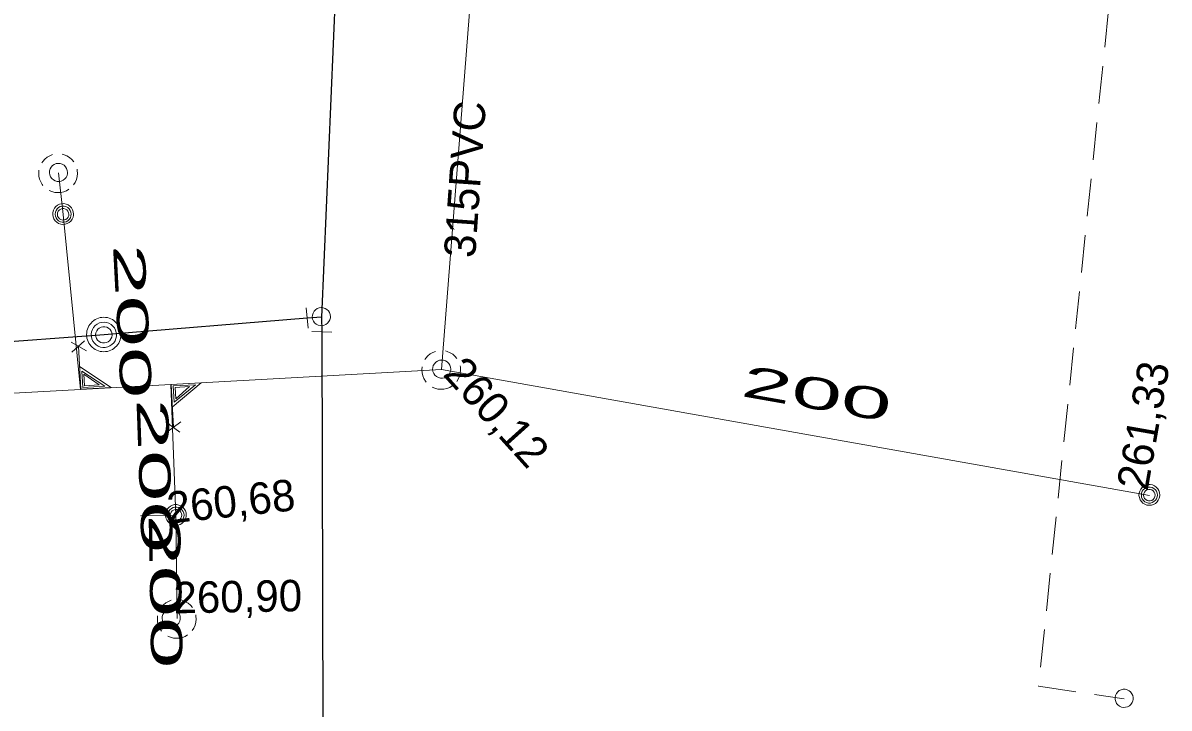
# Model space of a CAD drawing. Extents: x -732096 to -731933, y -1048703 to -1047964.
# Drawn here: x -732046.89 to -732017.73, y -1048047.02 to -1048029.6 of the extents above; entities that cross this region are included whole.
import ezdxf

# ---------------------------------------------------------------- set-up
doc = ezdxf.new("R2010")
doc.units = 0
doc.header["$LTSCALE"] = 0.32
doc.linetypes.add('MEDIUM_DASHED', pattern=[4.5, 3, -1.5])
doc.layers.add('1', color=7, linetype='Continuous')
for name, color, linetype, lineweight in [('18', 7, 'Continuous', 13), ('20', 7, 'Continuous', 13), ('49', 7, 'Continuous', 13), ('8', 7, 'Continuous', 13)]:
    doc.layers.add(name, color=color, linetype=linetype, lineweight=lineweight)

msp = doc.modelspace()

# ---------------------------------------------------------------- linework, layer by layer
at = {"layer": '18'}
for p, q in [((-732045.326, -1048037.679), (-732045.646, -1048037.966)), ((-732045.664, -1048037.71), (-732045.28, -1048037.934)), ((-732042.897, -1048039.999), (-732043.246, -1048039.749)), ((-732043.235, -1048040.006), (-732042.878, -1048039.742))]:
    msp.add_line(p, q, dxfattribs=at)
for points in [[(-732046.142, -1048032.947), (-732046.213, -1048032.975), (-732046.279, -1048033.014), (-732046.34, -1048033.062), (-732046.391, -1048033.119), (-732046.414, -1048033.153)], [(-732045.6, -1048033.13), (-732045.651, -1048033.072), (-732045.708, -1048033.022), (-732045.774, -1048032.981), (-732045.845, -1048032.952), (-732045.894, -1048032.938)], [(-732045.605, -1048033.716), (-732045.565, -1048033.651), (-732045.534, -1048033.581), (-732045.514, -1048033.506), (-732045.507, -1048033.43), (-732045.512, -1048033.353), (-732045.517, -1048033.318)], [(-732046.487, -1048033.339), (-732046.492, -1048033.416), (-732046.487, -1048033.493), (-732046.47, -1048033.568), (-732046.441, -1048033.639), (-732046.401, -1048033.705), (-732046.386, -1048033.727)], [(-732046.228, -1048033.856), (-732046.159, -1048033.887), (-732046.083, -1048033.906), (-732046.007, -1048033.913), (-732045.931, -1048033.908), (-732045.855, -1048033.891), (-732045.784, -1048033.863), (-732045.723, -1048033.828)], [(-732045.48, -1048037.816), (-732045.42, -1048038.911), (-732044.65, -1048038.868), (-732045.451, -1048038.334)], [(-732036.392, -1048037.947), (-732036.463, -1048037.975), (-732036.529, -1048038.014), (-732036.59, -1048038.062), (-732036.641, -1048038.119), (-732036.664, -1048038.153)], [(-732035.85, -1048038.13), (-732035.901, -1048038.072), (-732035.958, -1048038.022), (-732036.024, -1048037.981), (-732036.095, -1048037.952), (-732036.144, -1048037.938)], [(-732045.394, -1048038.449), (-732045.371, -1048038.864), (-732044.807, -1048038.833), (-732045.394, -1048038.448)], [(-732045.342, -1048038.53), (-732045.326, -1048038.82), (-732044.956, -1048038.8), (-732045.344, -1048038.53)], [(-732036.737, -1048038.339), (-732036.742, -1048038.416), (-732036.737, -1048038.493), (-732036.72, -1048038.568), (-732036.691, -1048038.639), (-732036.651, -1048038.705), (-732036.636, -1048038.727)], [(-732035.855, -1048038.716), (-732035.815, -1048038.651), (-732035.784, -1048038.581), (-732035.764, -1048038.506), (-732035.757, -1048038.43), (-732035.762, -1048038.353), (-732035.767, -1048038.318)], [(-732043.064, -1048039.879), (-732043.124, -1048038.786), (-732042.355, -1048038.744), (-732043.092, -1048039.363)], [(-732043.049, -1048039.241), (-732043.071, -1048038.827), (-732042.506, -1048038.796), (-732043.048, -1048039.243)], [(-732043.006, -1048039.156), (-732043.022, -1048038.864), (-732042.651, -1048038.844), (-732043.007, -1048039.156)], [(-732036.478, -1048038.856), (-732036.409, -1048038.887), (-732036.333, -1048038.906), (-732036.257, -1048038.913), (-732036.181, -1048038.908), (-732036.105, -1048038.891), (-732036.034, -1048038.863), (-732035.973, -1048038.828)], [(-732043.122, -1048044.277), (-732043.193, -1048044.305), (-732043.26, -1048044.344), (-732043.32, -1048044.392), (-732043.371, -1048044.449), (-732043.395, -1048044.483)], [(-732042.581, -1048044.46), (-732042.631, -1048044.402), (-732042.689, -1048044.352), (-732042.754, -1048044.311), (-732042.825, -1048044.282), (-732042.874, -1048044.268)], [(-732043.467, -1048044.669), (-732043.473, -1048044.746), (-732043.468, -1048044.823), (-732043.451, -1048044.898), (-732043.422, -1048044.969), (-732043.382, -1048045.035), (-732043.366, -1048045.057)], [(-732042.586, -1048045.046), (-732042.545, -1048044.981), (-732042.514, -1048044.911), (-732042.495, -1048044.836), (-732042.487, -1048044.76), (-732042.492, -1048044.683), (-732042.498, -1048044.648)], [(-732043.209, -1048045.186), (-732043.139, -1048045.217), (-732043.064, -1048045.236), (-732042.988, -1048045.243), (-732042.911, -1048045.238), (-732042.836, -1048045.221), (-732042.764, -1048045.193), (-732042.704, -1048045.158)]]:
    msp.add_lwpolyline(points, dxfattribs=at)
for points in [[(-732045.757, -1048033.399), (-732045.764, -1048033.347), (-732045.781, -1048033.297), (-732045.809, -1048033.253), (-732045.848, -1048033.216), (-732045.892, -1048033.189), (-732045.943, -1048033.173), (-732045.995, -1048033.168), (-732046.046, -1048033.175), (-732046.095, -1048033.194), (-732046.139, -1048033.224), (-732046.174, -1048033.263), (-732046.201, -1048033.308), (-732046.215, -1048033.359), (-732046.218, -1048033.411), (-732046.21, -1048033.463), (-732046.19, -1048033.511), (-732046.159, -1048033.554), (-732046.12, -1048033.589), (-732046.073, -1048033.613), (-732046.022, -1048033.627), (-732045.97, -1048033.629), (-732045.919, -1048033.619), (-732045.87, -1048033.597), (-732045.828, -1048033.565), (-732045.796, -1048033.525), (-732045.772, -1048033.478), (-732045.759, -1048033.427)], [(-732045.606, -1048034.457), (-732045.612, -1048034.401), (-732045.629, -1048034.348), (-732045.657, -1048034.299), (-732045.696, -1048034.258), (-732045.742, -1048034.226), (-732045.794, -1048034.204), (-732045.849, -1048034.193), (-732045.905, -1048034.195), (-732045.96, -1048034.208), (-732046.011, -1048034.233), (-732046.055, -1048034.268), (-732046.091, -1048034.311), (-732046.116, -1048034.361), (-732046.131, -1048034.416), (-732046.134, -1048034.472), (-732046.125, -1048034.527), (-732046.104, -1048034.58), (-732046.073, -1048034.626), (-732046.032, -1048034.665), (-732045.985, -1048034.695), (-732045.932, -1048034.714), (-732045.876, -1048034.721), (-732045.82, -1048034.717), (-732045.766, -1048034.7), (-732045.717, -1048034.673), (-732045.675, -1048034.635), (-732045.642, -1048034.59), (-732045.619, -1048034.539), (-732045.607, -1048034.484)], [(-732045.665, -1048034.46), (-732045.671, -1048034.411), (-732045.689, -1048034.365), (-732045.717, -1048034.324), (-732045.754, -1048034.291), (-732045.798, -1048034.269), (-732045.846, -1048034.257), (-732045.895, -1048034.257), (-732045.943, -1048034.269), (-732045.987, -1048034.292), (-732046.024, -1048034.325), (-732046.052, -1048034.366), (-732046.069, -1048034.413), (-732046.075, -1048034.462), (-732046.068, -1048034.511), (-732046.05, -1048034.557), (-732046.022, -1048034.597), (-732045.985, -1048034.63), (-732045.941, -1048034.652), (-732045.892, -1048034.664), (-732045.843, -1048034.663), (-732045.795, -1048034.651), (-732045.752, -1048034.627), (-732045.715, -1048034.594), (-732045.687, -1048034.553), (-732045.671, -1048034.506)], [(-732045.724, -1048034.464), (-732045.73, -1048034.422), (-732045.747, -1048034.384), (-732045.775, -1048034.353), (-732045.809, -1048034.33), (-732045.85, -1048034.319), (-732045.892, -1048034.319), (-732045.932, -1048034.331), (-732045.967, -1048034.354), (-732045.994, -1048034.386), (-732046.011, -1048034.424), (-732046.016, -1048034.465), (-732046.01, -1048034.507), (-732045.992, -1048034.544), (-732045.964, -1048034.576), (-732045.928, -1048034.598), (-732045.888, -1048034.609), (-732045.846, -1048034.608), (-732045.806, -1048034.595), (-732045.772, -1048034.572), (-732045.745, -1048034.539), (-732045.729, -1048034.501)], [(-732036.007, -1048038.399), (-732036.014, -1048038.347), (-732036.031, -1048038.297), (-732036.059, -1048038.253), (-732036.098, -1048038.216), (-732036.142, -1048038.189), (-732036.193, -1048038.173), (-732036.245, -1048038.168), (-732036.296, -1048038.175), (-732036.345, -1048038.194), (-732036.389, -1048038.224), (-732036.424, -1048038.263), (-732036.451, -1048038.308), (-732036.465, -1048038.359), (-732036.468, -1048038.411), (-732036.46, -1048038.463), (-732036.44, -1048038.511), (-732036.409, -1048038.554), (-732036.37, -1048038.589), (-732036.323, -1048038.613), (-732036.272, -1048038.627), (-732036.22, -1048038.629), (-732036.169, -1048038.619), (-732036.12, -1048038.597), (-732036.078, -1048038.565), (-732036.046, -1048038.525), (-732036.022, -1048038.478), (-732036.009, -1048038.427)], [(-732017.966, -1048041.597), (-732017.972, -1048041.541), (-732017.989, -1048041.488), (-732018.017, -1048041.439), (-732018.056, -1048041.398), (-732018.102, -1048041.366), (-732018.154, -1048041.344), (-732018.209, -1048041.333), (-732018.265, -1048041.335), (-732018.32, -1048041.348), (-732018.37, -1048041.373), (-732018.415, -1048041.408), (-732018.451, -1048041.451), (-732018.476, -1048041.501), (-732018.491, -1048041.556), (-732018.494, -1048041.612), (-732018.485, -1048041.667), (-732018.464, -1048041.72), (-732018.433, -1048041.766), (-732018.392, -1048041.805), (-732018.345, -1048041.835), (-732018.292, -1048041.854), (-732018.236, -1048041.861), (-732018.179, -1048041.857), (-732018.125, -1048041.84), (-732018.076, -1048041.813), (-732018.035, -1048041.775), (-732018.002, -1048041.73), (-732017.978, -1048041.679), (-732017.967, -1048041.624)], [(-732018.025, -1048041.6), (-732018.031, -1048041.551), (-732018.049, -1048041.505), (-732018.076, -1048041.464), (-732018.114, -1048041.431), (-732018.157, -1048041.409), (-732018.206, -1048041.397), (-732018.255, -1048041.397), (-732018.303, -1048041.409), (-732018.347, -1048041.432), (-732018.384, -1048041.465), (-732018.412, -1048041.506), (-732018.429, -1048041.553), (-732018.434, -1048041.602), (-732018.428, -1048041.651), (-732018.41, -1048041.697), (-732018.382, -1048041.737), (-732018.345, -1048041.77), (-732018.301, -1048041.792), (-732018.252, -1048041.804), (-732018.203, -1048041.803), (-732018.155, -1048041.791), (-732018.112, -1048041.767), (-732018.075, -1048041.734), (-732018.047, -1048041.693), (-732018.031, -1048041.646)], [(-732018.084, -1048041.604), (-732018.09, -1048041.562), (-732018.107, -1048041.524), (-732018.135, -1048041.493), (-732018.169, -1048041.47), (-732018.21, -1048041.459), (-732018.252, -1048041.459), (-732018.292, -1048041.471), (-732018.326, -1048041.494), (-732018.353, -1048041.526), (-732018.37, -1048041.564), (-732018.375, -1048041.605), (-732018.37, -1048041.647), (-732018.352, -1048041.684), (-732018.324, -1048041.716), (-732018.288, -1048041.738), (-732018.248, -1048041.749), (-732018.206, -1048041.748), (-732018.166, -1048041.735), (-732018.132, -1048041.712), (-732018.105, -1048041.679), (-732018.089, -1048041.641)], [(-732042.736, -1048042.107), (-732042.742, -1048042.051), (-732042.759, -1048041.998), (-732042.788, -1048041.949), (-732042.826, -1048041.908), (-732042.872, -1048041.876), (-732042.924, -1048041.854), (-732042.979, -1048041.843), (-732043.035, -1048041.845), (-732043.09, -1048041.858), (-732043.141, -1048041.883), (-732043.185, -1048041.918), (-732043.221, -1048041.961), (-732043.246, -1048042.011), (-732043.261, -1048042.066), (-732043.264, -1048042.122), (-732043.255, -1048042.177), (-732043.234, -1048042.23), (-732043.203, -1048042.276), (-732043.163, -1048042.315), (-732043.115, -1048042.345), (-732043.062, -1048042.364), (-732043.006, -1048042.371), (-732042.95, -1048042.367), (-732042.896, -1048042.35), (-732042.847, -1048042.323), (-732042.805, -1048042.285), (-732042.772, -1048042.24), (-732042.749, -1048042.189), (-732042.737, -1048042.134)], [(-732042.795, -1048042.11), (-732042.801, -1048042.061), (-732042.819, -1048042.015), (-732042.847, -1048041.974), (-732042.884, -1048041.941), (-732042.928, -1048041.919), (-732042.976, -1048041.907), (-732043.025, -1048041.907), (-732043.073, -1048041.919), (-732043.117, -1048041.942), (-732043.154, -1048041.975), (-732043.182, -1048042.016), (-732043.199, -1048042.063), (-732043.205, -1048042.112), (-732043.198, -1048042.161), (-732043.18, -1048042.207), (-732043.152, -1048042.247), (-732043.115, -1048042.28), (-732043.071, -1048042.302), (-732043.022, -1048042.314), (-732042.973, -1048042.313), (-732042.925, -1048042.301), (-732042.882, -1048042.277), (-732042.845, -1048042.244), (-732042.817, -1048042.203), (-732042.801, -1048042.156)], [(-732042.854, -1048042.114), (-732042.86, -1048042.072), (-732042.877, -1048042.034), (-732042.905, -1048042.003), (-732042.94, -1048041.98), (-732042.98, -1048041.969), (-732043.022, -1048041.969), (-732043.062, -1048041.981), (-732043.097, -1048042.004), (-732043.124, -1048042.036), (-732043.141, -1048042.074), (-732043.146, -1048042.115), (-732043.14, -1048042.157), (-732043.122, -1048042.194), (-732043.094, -1048042.226), (-732043.058, -1048042.248), (-732043.018, -1048042.259), (-732042.976, -1048042.258), (-732042.936, -1048042.245), (-732042.902, -1048042.222), (-732042.875, -1048042.189), (-732042.859, -1048042.151)], [(-732042.889, -1048044.729), (-732042.895, -1048044.677), (-732042.913, -1048044.627), (-732042.941, -1048044.583), (-732042.979, -1048044.546), (-732043.024, -1048044.519), (-732043.074, -1048044.503), (-732043.126, -1048044.498), (-732043.178, -1048044.505), (-732043.227, -1048044.524), (-732043.271, -1048044.554), (-732043.306, -1048044.593), (-732043.332, -1048044.638), (-732043.347, -1048044.689), (-732043.35, -1048044.741), (-732043.342, -1048044.793), (-732043.321, -1048044.841), (-732043.291, -1048044.884), (-732043.251, -1048044.919), (-732043.205, -1048044.943), (-732043.154, -1048044.957), (-732043.102, -1048044.959), (-732043.05, -1048044.949), (-732043.002, -1048044.927), (-732042.96, -1048044.895), (-732042.927, -1048044.855), (-732042.903, -1048044.808), (-732042.891, -1048044.757)]]:
    msp.add_lwpolyline(points, close=True, dxfattribs=at)
at = {"layer": '20'}
msp.add_lwpolyline([(-732072.387, -1048040.394), (-732045.426, -1048038.914), (-732043.129, -1048038.788), (-732036.239, -1048038.41), (-732035.469, -1048028.56)], dxfattribs=at)
msp.add_lwpolyline([(-732072.387, -1048040.394), (-732045.426, -1048038.914), (-732043.129, -1048038.788), (-732036.239, -1048038.41), (-732035.469, -1048028.56)], dxfattribs=at)
at = {"layer": '49'}
for p, q in [((-732018.23, -1048041.61), (-732036.239, -1048038.41)), ((-732018.23, -1048041.61), (-732036.239, -1048038.41)), ((-732043, -1048042.12), (-732043.129, -1048038.788)), ((-732043, -1048042.12), (-732043.129, -1048038.788)), ((-732043.899, -1048042.13), (-732043, -1048042.12)), ((-732043.899, -1048042.13), (-732043, -1048042.12)), ((-732042.969, -1048044.74), (-732043, -1048042.12)), ((-732042.969, -1048044.74), (-732043, -1048042.12))]:
    msp.add_line(p, q, dxfattribs=at)
msp.add_lwpolyline([(-732045.989, -1048033.41), (-732045.87, -1048034.47), (-732045.426, -1048038.914)], dxfattribs=at)
msp.add_lwpolyline([(-732045.989, -1048033.41), (-732045.87, -1048034.47), (-732045.426, -1048038.914)], dxfattribs=at)
at = {"layer": '8', "lineweight": 25}
for p, q in [((-732039.66, -1048037.1), (-732044.829, -1048037.53)), ((-732039.3, -1048037.077), (-732039.66, -1048037.1)), ((-732039.3, -1048037.077), (-732039.289, -1048037.45))]:
    msp.add_line(p, q, dxfattribs=at)
at = {"layer": '8'}
for p, q in [((-732039.636, -1048037.358), (-732039.683, -1048036.843)), ((-732039.029, -1048037.457), (-732039.546, -1048037.442))]:
    msp.add_line(p, q, dxfattribs=at)
at = {"layer": '8', "lineweight": 25}
for points in [[(-732033.399, -1047999.11), (-732033.26, -1048005.79), (-732035.475, -1048012.689), (-732038.309, -1048021.518), (-732038.774, -1048026.833), (-732038.94, -1048028.735), (-732039.3, -1048037.077)], [(-732044.829, -1048037.53), (-732057.629, -1048038.48), (-732069.423, -1048038.886), (-732072.139, -1048038.979)], [(-732039.289, -1048037.45), (-732039.26, -1048047.48), (-732037.5, -1048060.59), (-732034.1, -1048071.04), (-732029.18, -1048078.35)]]:
    msp.add_lwpolyline(points, dxfattribs=at)
at = {"layer": '8', "linetype": 'MEDIUM_DASHED'}
msp.add_lwpolyline([(-732019.12, -1048027.83), (-732021.05, -1048046.46), (-732018.874, -1048046.779)], dxfattribs=at)
at = {"layer": '8'}
msp.add_lwpolyline([(-732044.399, -1048037.519), (-732044.401, -1048037.474), (-732044.408, -1048037.429), (-732044.42, -1048037.384), (-732044.436, -1048037.342), (-732044.457, -1048037.301), (-732044.482, -1048037.262), (-732044.511, -1048037.227), (-732044.543, -1048037.194), (-732044.579, -1048037.166), (-732044.617, -1048037.141), (-732044.658, -1048037.12), (-732044.701, -1048037.103), (-732044.745, -1048037.091), (-732044.79, -1048037.084), (-732044.836, -1048037.082), (-732044.882, -1048037.084), (-732044.927, -1048037.091), (-732044.971, -1048037.103), (-732045.014, -1048037.12), (-732045.055, -1048037.141), (-732045.093, -1048037.166), (-732045.129, -1048037.194), (-732045.161, -1048037.227), (-732045.19, -1048037.262), (-732045.215, -1048037.301), (-732045.236, -1048037.342), (-732045.252, -1048037.384), (-732045.264, -1048037.429), (-732045.271, -1048037.474), (-732045.274, -1048037.52), (-732045.271, -1048037.565), (-732045.264, -1048037.61), (-732045.252, -1048037.655), (-732045.236, -1048037.697), (-732045.215, -1048037.738), (-732045.19, -1048037.777), (-732045.161, -1048037.812), (-732045.129, -1048037.845), (-732045.093, -1048037.873), (-732045.055, -1048037.898), (-732045.014, -1048037.919), (-732044.971, -1048037.936), (-732044.927, -1048037.947), (-732044.882, -1048037.955), (-732044.836, -1048037.957), (-732044.79, -1048037.955), (-732044.745, -1048037.947), (-732044.701, -1048037.936), (-732044.658, -1048037.919), (-732044.617, -1048037.898), (-732044.579, -1048037.873), (-732044.543, -1048037.845), (-732044.511, -1048037.812), (-732044.482, -1048037.777), (-732044.457, -1048037.738), (-732044.436, -1048037.697), (-732044.42, -1048037.655), (-732044.408, -1048037.61), (-732044.401, -1048037.565), (-732044.399, -1048037.52)], dxfattribs=at)
for points in [[(-732039.069, -1048037.066), (-732039.075, -1048037.014), (-732039.093, -1048036.964), (-732039.121, -1048036.92), (-732039.159, -1048036.883), (-732039.204, -1048036.856), (-732039.254, -1048036.84), (-732039.306, -1048036.835), (-732039.358, -1048036.842), (-732039.407, -1048036.861), (-732039.451, -1048036.891), (-732039.486, -1048036.93), (-732039.512, -1048036.975), (-732039.527, -1048037.026), (-732039.53, -1048037.078), (-732039.522, -1048037.13), (-732039.501, -1048037.178), (-732039.471, -1048037.221), (-732039.431, -1048037.256), (-732039.385, -1048037.28), (-732039.334, -1048037.294), (-732039.282, -1048037.296), (-732039.23, -1048037.286), (-732039.182, -1048037.264), (-732039.14, -1048037.232), (-732039.107, -1048037.192), (-732039.083, -1048037.145), (-732039.071, -1048037.094)], [(-732044.512, -1048037.527), (-732044.518, -1048037.466), (-732044.536, -1048037.406), (-732044.565, -1048037.351), (-732044.604, -1048037.303), (-732044.651, -1048037.263), (-732044.705, -1048037.233), (-732044.764, -1048037.213), (-732044.826, -1048037.206), (-732044.888, -1048037.21), (-732044.948, -1048037.226), (-732045.003, -1048037.254), (-732045.053, -1048037.291), (-732045.094, -1048037.338), (-732045.126, -1048037.391), (-732045.146, -1048037.45), (-732045.156, -1048037.511), (-732045.153, -1048037.573), (-732045.138, -1048037.633), (-732045.112, -1048037.69), (-732045.076, -1048037.74), (-732045.03, -1048037.783), (-732044.978, -1048037.815), (-732044.92, -1048037.838), (-732044.859, -1048037.848), (-732044.797, -1048037.847), (-732044.736, -1048037.834), (-732044.679, -1048037.809), (-732044.628, -1048037.774), (-732044.584, -1048037.73), (-732044.55, -1048037.678), (-732044.526, -1048037.621), (-732044.514, -1048037.56)], [(-732044.626, -1048037.527), (-732044.632, -1048037.478), (-732044.649, -1048037.431), (-732044.677, -1048037.39), (-732044.715, -1048037.357), (-732044.759, -1048037.333), (-732044.807, -1048037.321), (-732044.857, -1048037.32), (-732044.905, -1048037.332), (-732044.95, -1048037.354), (-732044.988, -1048037.387), (-732045.017, -1048037.427), (-732045.036, -1048037.474), (-732045.043, -1048037.523), (-732045.038, -1048037.573), (-732045.021, -1048037.62), (-732044.994, -1048037.662), (-732044.957, -1048037.696), (-732044.914, -1048037.72), (-732044.866, -1048037.734), (-732044.816, -1048037.735), (-732044.767, -1048037.725), (-732044.722, -1048037.703), (-732044.683, -1048037.671), (-732044.653, -1048037.632), (-732044.634, -1048037.586), (-732044.626, -1048037.536)], [(-732018.643, -1048046.802), (-732018.642, -1048046.749), (-732018.652, -1048046.697), (-732018.674, -1048046.65), (-732018.706, -1048046.607), (-732018.747, -1048046.574), (-732018.794, -1048046.551), (-732018.844, -1048046.539), (-732018.897, -1048046.538), (-732018.948, -1048046.55), (-732018.996, -1048046.573), (-732019.036, -1048046.607), (-732019.069, -1048046.647), (-732019.091, -1048046.696), (-732019.101, -1048046.747), (-732019.101, -1048046.799), (-732019.087, -1048046.85), (-732019.064, -1048046.897), (-732019.029, -1048046.937), (-732018.987, -1048046.968), (-732018.939, -1048046.989), (-732018.888, -1048046.998), (-732018.835, -1048046.996), (-732018.784, -1048046.981), (-732018.738, -1048046.956), (-732018.699, -1048046.921), (-732018.669, -1048046.878), (-732018.649, -1048046.829)]]:
    msp.add_lwpolyline(points, close=True, dxfattribs=at)

# ---------------------------------------------------------------- texts
at = {"layer": '1'}
for s, rotation, p in [('315PVC', 86, (-732035.387, -1048035.587)), ('260,12', 312, (-732036.227, -1048038.542)), ('261,33', 80, (-732018.277, -1048041.512)), ('260,68', 6, (-732043.188, -1048042.326)), ('260,90', 1, (-732043.055, -1048044.609))]:
    msp.add_text(s, height=0.8, rotation=rotation, dxfattribs=at).set_placement(p)
for rotation, width, p in [(273, 2.2, (-732044.604, -1048035.241)), (350, 2.15, (-732028.651, -1048039.079)), (272, 2.2, (-732044.006, -1048039.162)), (271, 2.2, (-732043.696, -1048042.09))]:
    msp.add_text('200 ', height=0.8, rotation=rotation, dxfattribs=dict(at, width=width)).set_placement(p)

doc.saveas('drawing.dxf')
